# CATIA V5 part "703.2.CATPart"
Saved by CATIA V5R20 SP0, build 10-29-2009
Part number: 703.2
Revision: QUALSIASI
Definition: SCONOSCIUTO
Nomenclature: 703.2
Source: Unknown
Bounding box of the stored display mesh (mm): x -50 to 50, y -50 to 50, z 0 to 30
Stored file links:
  C:\Users\Utente\Desktop\IO LAVORO\3D X SITO CF\X 3D SITO CF 27-09-2020\703\703.2.CATPart
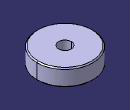
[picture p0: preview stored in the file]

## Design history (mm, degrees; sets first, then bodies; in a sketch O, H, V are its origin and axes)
Body1 "NONE" (main body)
  Solid1: solid without history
